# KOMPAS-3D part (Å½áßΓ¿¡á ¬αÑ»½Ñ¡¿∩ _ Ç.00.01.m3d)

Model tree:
1. Эскиз:1
2. Операция выдавливания:1
     Расстояние 1 = 5
3. Эскиз:2
4. Вырезать элемент выдавливания:1
     Расстояние 1 = 10
5. Эскиз:3
6. Эскиз:6
7. Вырезать элемент выдавливания:4  (labels: А.00.01)
     Расстояние 1 = 0.1

Referenced files in C:\Users\s.slezkin\Desktop\Раскатчик арок 2\: Пластина крепления _ А.00.01.m3d
Referenced files: graphic.tdp
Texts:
  Body Specification ( left align )
  Body Specificaton ( centered )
